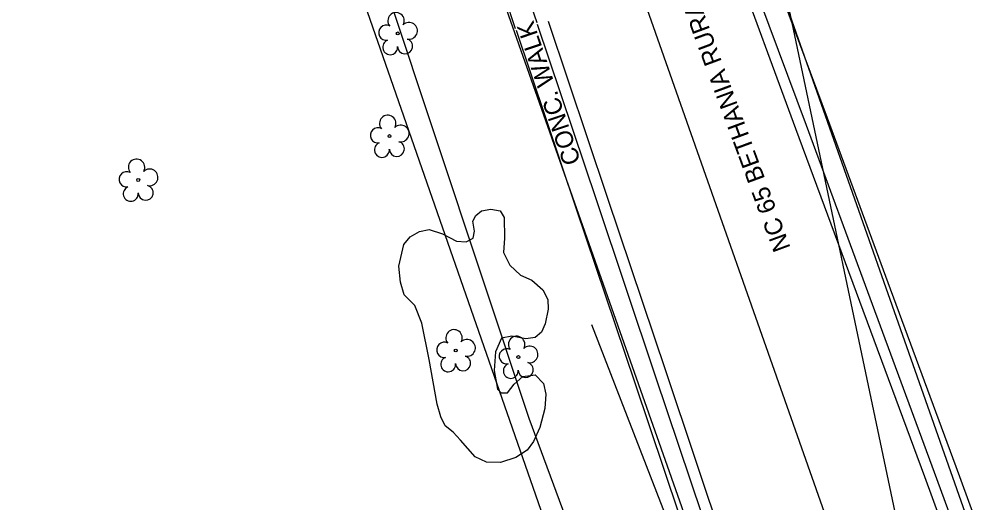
# Model space of a CAD drawing. Extents: x 1611576 to 1617186, y 899279 to 905462.
# Drawn here: x 1615954.6 to 1616172.8, y 904169.2 to 904278.6 of the extents above; entities that cross this region are included whole.
import ezdxf

# ---------------------------------------------------------------- set-up
doc = ezdxf.new("R2010")
doc.units = 0
for name, color, linetype in [('Exist Horizontal Alignment', 7, 'Continuous'), ('Exist Right of Way Line', 7, 'Continuous'), ('Exist Roads Curbs', 7, 'Continuous'), ('Exist Roads EOP', 7, 'Continuous'), ('Exist Roads EOP Other', 7, 'Continuous'), ('Exist Roads EOP Other Text', 7, 'Continuous'), ('Exist Roads EOP Text', 7, 'Continuous'), ('Exist Structure Minor Pipes RCP 18 Inch', 7, 'Continuous'), ('Exist Vegetation Hedge Row', 7, 'Continuous'), ('Exist Vegetation Tree CELL', 7, 'Continuous'), ('Prop 6 In Gas Line (B2)', 7, 'Continuous'), ('Prop OH Pow Tel CATV Lines', 7, 'Continuous')]:
    doc.layers.add(name, color=color, linetype=linetype)

msp = doc.modelspace()

# ---------------------------------------------------------------- linework, layer by layer
at = {"layer": 'Exist Horizontal Alignment'}
msp.add_line((1616145.53, 904142.15), (1616079.93, 904328.43), dxfattribs=at)
at = {"layer": 'Exist Right of Way Line'}
for p, q in [((1615887.44, 905426.15), (1616864.55, 900788.06)), ((1616173.83, 904152.11), (1616108.23, 904338.4)), ((1616117.23, 904132.18), (1616051.63, 904318.47))]:
    msp.add_line(p, q, dxfattribs=at)
at = {"layer": 'Exist Roads Curbs'}
msp.add_line((1616057.52, 904320.31), (1616071.65, 904277.84), dxfattribs=at)
for points in [[(1616117.86, 904294.32), (1616132.6, 904254.66), (1616147.03, 904215.59), (1616161.55, 904176.09), (1616175.82, 904137.25), (1616190.47, 904097.09), (1616204.98, 904057.33), (1616219.73, 904016.73), (1616233.88, 903976.63), (1616247.93, 903936.53), (1616261.75, 903896.6), (1616275.82, 903856.12), (1616289.5, 903816.57), (1616303.58, 903775.98), (1616318, 903734.48)], [(1616071.77, 904277.47), (1616085.18, 904237.58), (1616098.48, 904197.94), (1616111.7, 904158.5), (1616117.5, 904141.64)]]:
    msp.add_lwpolyline(points, dxfattribs=at)
at = {"layer": 'Exist Roads EOP'}
for points in [[(1616115.61, 904293.45), (1616130.22, 904253.88), (1616144.71, 904214.78), (1616159.36, 904175.17), (1616173.54, 904136.33), (1616188.19, 904096.22), (1616202.56, 904056.51), (1616217.36, 904015.9), (1616231.52, 903975.89), (1616245.62, 903935.7), (1616259.38, 903895.73), (1616273.35, 903855.36), (1616287.12, 903815.79), (1616301.21, 903775.08), (1616315.66, 903733.58)], [(1616115.61, 904293.45), (1616130.22, 904253.88), (1616144.71, 904214.78), (1616159.36, 904175.17), (1616173.54, 904136.33), (1616188.19, 904096.22), (1616202.56, 904056.51), (1616217.36, 904015.9), (1616231.52, 903975.89), (1616245.62, 903935.7), (1616259.38, 903895.73), (1616273.35, 903855.36), (1616287.12, 903815.79)], [(1616074.22, 904278.19), (1616087.6, 904238.34), (1616100.83, 904198.88), (1616114.11, 904159.22), (1616119.62, 904142.34)]]:
    msp.add_lwpolyline(points, dxfattribs=at)
at = {"layer": 'Exist Roads EOP Other'}
msp.add_line((1616066.88, 904276.41), (1616052.78, 904318.7), dxfattribs=at)
for points in [[(1616122.43, 904296.46), (1616137.34, 904256.3), (1616151.63, 904217.58), (1616166.45, 904177.4), (1616180.52, 904139.04), (1616195.16, 904098.73), (1616209.58, 904059.11), (1616224.45, 904018.46), (1616238.58, 903978.47), (1616252.68, 903938.24), (1616266.45, 903898.41), (1616280.47, 903857.78), (1616294.14, 903818.38), (1616308.3, 903777.63), (1616322.66, 903736.35)], [(1616066.97, 904276.15), (1616080.53, 904235.92), (1616093.82, 904196.35), (1616107.14, 904156.8), (1616112.75, 904140.23)]]:
    msp.add_lwpolyline(points, dxfattribs=at)
at = {"layer": 'Exist Structure Minor Pipes RCP 18 Inch'}
msp.add_line((1616084.02, 904209.5), (1616168.38, 903992.15), dxfattribs=at)
msp.add_line((1616084.02, 904209.5), (1616168.38, 903992.15), dxfattribs=at)
at = {"layer": 'Exist Vegetation Hedge Row'}
msp.add_lwpolyline([(1616066.92, 904179.47), (1616063.42, 904178.29), (1616060.29, 904178.37), (1616057.73, 904179.57), (1616054.39, 904183.37), (1616052.72, 904185.14), (1616050.9, 904186.62), (1616049.97, 904188.66), (1616049.09, 904191.52), (1616047.31, 904201.65), (1616045.67, 904209.87), (1616044.07, 904213.85), (1616041.69, 904216.27), (1616040.86, 904219.09), (1616040.47, 904222.76), (1616041.57, 904227.66), (1616043.02, 904229.39), (1616045.1, 904230.55), (1616047.32, 904231.06), (1616050.32, 904230.01), (1616053.51, 904228.39), (1616055.7, 904228.27), (1616057.25, 904229.03), (1616057.58, 904230.63), (1616057.21, 904232.89), (1616057.84, 904234.21), (1616059.13, 904235.27), (1616061.24, 904235.63), (1616063.35, 904235.27), (1616064.31, 904233.76), (1616064.35, 904229.1), (1616064.15, 904225.85), (1616065.54, 904222.99), (1616067.99, 904220.67), (1616070.55, 904219.55), (1616073.02, 904217.4), (1616074.16, 904215.17), (1616074.27, 904213.02), (1616073.54, 904209.67), (1616072.74, 904207.78), (1616071.31, 904206.61), (1616069.21, 904206.27), (1616066.04, 904206.89), (1616063.68, 904206.43), (1616062.35, 904203.38), (1616062.04, 904199.09), (1616062.75, 904194.92), (1616063.59, 904194.09), (1616065.07, 904194.08), (1616066.52, 904196.05), (1616068.49, 904197.76), (1616071.31, 904198.12), (1616073.21, 904196.2), (1616073.71, 904193.77), (1616073.46, 904190.53), (1616072.33, 904186.21), (1616070.89, 904183.06), (1616069.47, 904181.12), (1616066.92, 904179.47)], dxfattribs=at)
at = {"layer": 'Exist Vegetation Tree CELL'}
for p, q in [((1616040.2, 904275.39), (1616040.2, 904275.39)), ((1616038.33, 904252.16), (1616038.33, 904252.16)), ((1615981.5, 904242.23), (1615981.5, 904242.23)), ((1616053.32, 904203.64), (1616053.32, 904203.64)), ((1616067.49, 904202.16), (1616067.49, 904202.16))]:
    msp.add_line(p, q, dxfattribs=at)
for centre in [(1616040.2, 904275.39), (1616038.33, 904252.16), (1615981.5, 904242.23), (1616053.32, 904203.64), (1616067.49, 904202.16)]:
    msp.add_circle(centre, 0.326, dxfattribs=at)
for centre, radius, start, end in [((1616039.82, 904278.26), 1.86, 330.1651, 219.7134), ((1616037.6, 904275.54), 1.73, 62.6636, 279.3457), ((1616042.75, 904275.98), 1.9, 257.1011, 134.1999), ((1616041.87, 904272.49), 1.7, 181.2822, 74.56), ((1616038.5, 904272.27), 1.69, 111.5671, 6.231), ((1616037.94, 904255.03), 1.86, 330.1651, 219.7134), ((1616040.87, 904252.75), 1.9, 257.1011, 134.1999), ((1616035.72, 904252.31), 1.73, 62.6636, 279.3457), ((1616036.62, 904249.04), 1.69, 111.5671, 6.231), ((1616040, 904249.26), 1.7, 181.2822, 74.56), ((1615981.11, 904245.1), 1.86, 330.1651, 219.7134), ((1615978.89, 904242.38), 1.73, 62.6636, 279.3457), ((1615984.05, 904242.81), 1.9, 257.1011, 134.1999), ((1615979.79, 904239.1), 1.69, 111.5671, 6.231), ((1615983.17, 904239.33), 1.7, 181.2822, 74.56), ((1616052.94, 904206.51), 1.86, 330.1651, 219.7134), ((1616067.1, 904205.03), 1.86, 330.1651, 219.7134), ((1616050.72, 904203.79), 1.73, 62.6636, 279.3457), ((1616055.87, 904204.23), 1.9, 257.1011, 134.1999), ((1616070.03, 904202.75), 1.9, 257.1011, 134.1999), ((1616051.62, 904200.52), 1.69, 111.5671, 6.231), ((1616055, 904200.74), 1.7, 181.2822, 74.56), ((1616064.88, 904202.31), 1.73, 62.6636, 279.3457), ((1616065.78, 904199.04), 1.69, 111.5671, 6.231), ((1616069.16, 904199.26), 1.7, 181.2822, 74.56)]:
    msp.add_arc(centre, radius, start, end, dxfattribs=at)
at = {"layer": 'Prop 6 In Gas Line (B2)'}
for p, q in [((1616069.92, 904188.28), (1616014.2, 904356.06)), ((1616129.25, 904028.65), (1616069.92, 904188.28))]:
    msp.add_line(p, q, dxfattribs=at)
at = {"layer": 'Prop OH Pow Tel CATV Lines'}
msp.add_line((1616084.75, 904132.64), (1616001.87, 904370.71), dxfattribs=at)

# ---------------------------------------------------------------- texts
at = {"layer": 'Exist Roads EOP Other Text'}
msp.add_text('CONC. WALK', height=4, rotation=108.6278, dxfattribs=at).set_placement((1616081.66, 904246.4))
at = {"layer": 'Exist Roads EOP Text'}
msp.add_text('NC 65 BETHANIA RURAL HALL RD.', height=4, rotation=110.2637, dxfattribs=at).set_placement((1616129.13, 904226.89))

doc.saveas('drawing.dxf')
